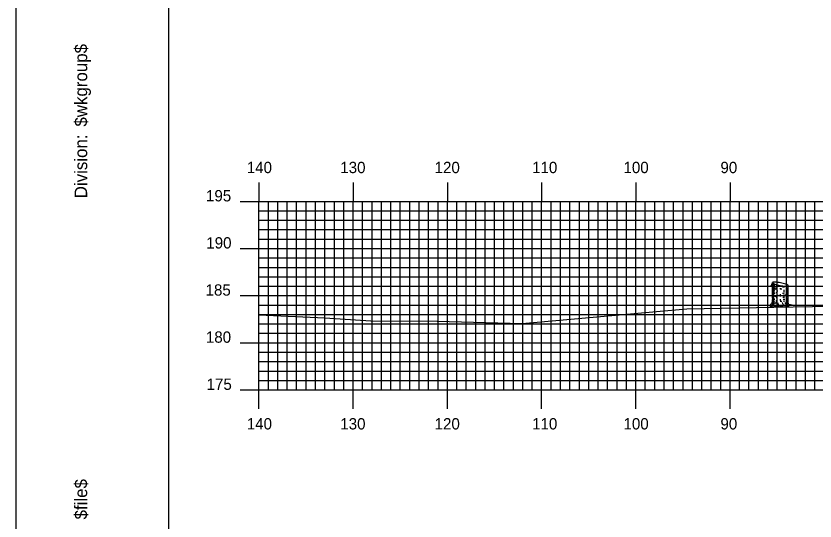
# Model space of a CAD drawing. Extents: x 1825540 to 1825883, y 442591 to 442811.
# Drawn here: x 1825540.1 to 1825624.9, y 442644.7 to 442698.3 of the extents above; entities that cross this region are included whole.
import ezdxf

# ---------------------------------------------------------------- set-up
doc = ezdxf.new("R2010")
doc.units = 0
for name, color, linetype in [('BORDER', 7, 'Continuous'), ('H_V ANNOTATION', 7, 'Continuous'), ('M_Trees_Conifer_Pay', 7, 'Continuous'), ('MAJOR', 7, 'Continuous'), ('MINOR', 7, 'Continuous'), ('PLOT BOUNDARY', 7, 'Continuous'), ('S_Roadway_Centerline', 7, 'Continuous')]:
    doc.layers.add(name, color=color, linetype=linetype)

msp = doc.modelspace()

# ---------------------------------------------------------------- linework, layer by layer
at = {"layer": 'BORDER'}
msp.add_lwpolyline([(1825556.274, 442596.665), (1825876.274, 442596.665), (1825876.274, 442806.665), (1825556.274, 442806.665)], close=True, dxfattribs=at)
at = {"layer": 'M_Trees_Conifer_Pay'}
for p, q in [((1825620.375, 442668.404), (1825620.375, 442670.051)), ((1825620.447, 442669.979), (1825620.447, 442669.816)), ((1825620.564, 442669.918), (1825620.564, 442669.695)), ((1825620.447, 442669.749), (1825620.447, 442669.621)), ((1825620.447, 442669.434), (1825620.447, 442669.098)), ((1825620.447, 442669.061), (1825620.447, 442668.898)), ((1825620.507, 442669.423), (1825620.558, 442669.363)), ((1825620.564, 442669.606), (1825620.564, 442669.559)), ((1825620.564, 442669.224), (1825620.564, 442669.092)), ((1825620.793, 442669.722), (1825620.793, 442669.522)), ((1825620.793, 442669.465), (1825620.793, 442669.376)), ((1825620.793, 442669.028), (1825620.793, 442668.923)), ((1825621.183, 442669.448), (1825621.183, 442669.353)), ((1825621.589, 442669.68), (1825621.589, 442669.512)), ((1825621.589, 442669.275), (1825621.589, 442669.038)), ((1825621.808, 442669.659), (1825621.808, 442669.427)), ((1825621.808, 442669.386), (1825621.808, 442669.312)), ((1825621.934, 442669.667), (1825621.934, 442669.57)), ((1825621.934, 442669.495), (1825621.934, 442669.291)), ((1825621.934, 442669.234), (1825621.934, 442669.034)), ((1825621.992, 442669.678), (1825621.992, 442669.207)), ((1825621.992, 442669.143), (1825621.992, 442668.835)), ((1825622.039, 442667.994), (1825622.039, 442669.716)), ((1825620.447, 442668.851), (1825620.447, 442668.634)), ((1825620.447, 442668.604), (1825620.447, 442668.53)), ((1825620.447, 442668.489), (1825620.447, 442668.316)), ((1825620.564, 442668.981), (1825620.564, 442668.871)), ((1825620.564, 442668.736), (1825620.564, 442668.594)), ((1825620.564, 442668.367), (1825620.564, 442668.194)), ((1825620.793, 442668.556), (1825620.793, 442668.41)), ((1825620.793, 442668.178), (1825620.793, 442668.089)), ((1825621.183, 442668.835), (1825621.183, 442668.76)), ((1825621.183, 442668.736), (1825621.183, 442668.587)), ((1825621.183, 442668.295), (1825621.183, 442668.142)), ((1825621.589, 442668.793), (1825621.589, 442668.641)), ((1825621.589, 442668.598), (1825621.589, 442668.425)), ((1825621.589, 442668.147), (1825621.589, 442667.994)), ((1825621.808, 442668.909), (1825621.808, 442668.77)), ((1825621.808, 442668.499), (1825621.808, 442668.357)), ((1825621.934, 442668.987), (1825621.934, 442668.651)), ((1825621.934, 442668.598), (1825621.934, 442668.462)), ((1825621.934, 442668.363), (1825621.934, 442667.984)), ((1825621.992, 442668.787), (1825621.992, 442668.295)), ((1825621.992, 442668.241), (1825621.992, 442667.994)), ((1825621.371, 442667.537), (1825621.497, 442667.601)), ((1825621.808, 442667.601), (1825621.646, 442667.665)), ((1825621.808, 442668.095), (1825621.808, 442668.001))]:
    msp.add_line(p, q, dxfattribs=at)
for points in [[(1825620.558, 442669.549), (1825620.522, 442669.475), (1825620.474, 442669.532), (1825620.417, 442669.6), (1825620.324, 442669.794), (1825620.26, 442669.841), (1825620.229, 442669.848)], [(1825620.329, 442669.782), (1825620.254, 442669.79), (1825620.182, 442669.691)], [(1825620.544, 442669.296), (1825620.507, 442669.423), (1825620.444, 442669.539), (1825620.413, 442669.606), (1825620.344, 442669.753)], [(1825620.592, 442669.512), (1825620.623, 442669.427), (1825620.627, 442669.36), (1825620.596, 442669.296)], [(1825621.86, 442669.022), (1825621.866, 442669.117), (1825621.823, 442669.094), (1825621.823, 442668.999)], [(1825620.375, 442668.404), (1825620.324, 442668.142), (1825620.308, 442667.869), (1825620.25, 442667.743), (1825620.114, 442667.713), (1825620.344, 442667.675), (1825620.344, 442667.675), (1825620.339, 442667.628), (1825620.091, 442667.533), (1825620.365, 442667.55), (1825620.721, 442667.57), (1825621.043, 442667.56), (1825621.036, 442667.642), (1825621.184, 442667.56), (1825621.371, 442667.537), (1825621.347, 442667.469), (1825621.615, 442667.512), (1825621.835, 442667.486), (1825622.128, 442667.503), (1825621.839, 442667.56), (1825621.808, 442667.601), (1825621.971, 442667.659), (1825622.208, 442667.669), (1825622.449, 442667.669), (1825622.107, 442667.727), (1825622.066, 442667.807), (1825622.039, 442667.994)], [(1825620.449, 442668.262), (1825620.444, 442668.116), (1825620.396, 442668.048), (1825620.386, 442667.848)], [(1825620.721, 442668.623), (1825620.709, 442668.546), (1825620.661, 442668.556), (1825620.674, 442668.723)], [(1825620.549, 442668.116), (1825620.474, 442668.011), (1825620.47, 442667.838), (1825620.344, 442667.675)], [(1825620.507, 442667.622), (1825620.522, 442667.76), (1825620.596, 442667.889)], [(1825620.785, 442668.011), (1825620.775, 442667.885), (1825620.701, 442667.842)], [(1825621.036, 442667.642), (1825620.962, 442667.784), (1825620.952, 442667.885)], [(1825621.524, 442667.713), (1825621.457, 442667.807), (1825621.43, 442667.947)], [(1825621.751, 442667.953), (1825621.751, 442667.821), (1825621.839, 442667.722)], [(1825621.913, 442667.926), (1825621.907, 442667.811), (1825621.961, 442667.722), (1825621.971, 442667.659)], [(1825621.991, 442667.947), (1825622.012, 442667.869), (1825622.033, 442667.774)]]:
    msp.add_lwpolyline(points, dxfattribs=at)
for centre, radius, start, end in [((1825620.398, 442670.051), 0.0226, 168.2806, 179.96855), ((1825620.402, 442670.051), 0.0264, 179.96855, 190.7806), ((1825620.408, 442669.925), 0.0334, 185.78494, 196.05154), ((1825620.398, 442670.051), 0.0226, 156.59265, 168.2806), ((1825620.407, 442670.052), 0.0314, 190.7806, 203.48418), ((1825620.419, 442669.928), 0.0441, 196.05154, 210), ((1825620.401, 442670.05), 0.0264, 145.7806, 156.59265), ((1825620.426, 442670.061), 0.0527, 203.48418, 213.2806), ((1825620.405, 442670.047), 0.0314, 133.07702, 145.7806), ((1825620.435, 442669.937), 0.0624, 210, 228.74941), ((1825620.45, 442670.077), 0.0817, 213.2806, 227.61132), ((1825620.42, 442670.031), 0.0527, 123.2806, 133.07702), ((1825620.436, 442670.007), 0.0817, 108.94987, 123.2806), ((1825620.507, 442670.02), 0.172, 228.74941, 240), ((1825620.564, 442670.201), 0.251, 227.61132, 235.7806), ((1825620.491, 442669.848), 0.251, 100.7806, 108.94987), ((1825620.874, 442670.657), 0.802, 235.7806, 251.94061), ((1825620.594, 442669.306), 0.802, 84.62059, 100.7806), ((1825622.231, 442674.819), 5.179, 251.94061, 258.2806), ((1825620.183, 442664.948), 5.179, 78.2806, 84.62059), ((1825620.183, 442664.948), 5.179, 71.94061, 78.2806), ((1825621.54, 442669.11), 0.802, 55.7806, 71.94061), ((1825620.408, 442669.77), 0.0334, 185.78494, 196.05154), ((1825620.409, 442669.327), 0.0334, 185.78494, 196.05154), ((1825620.419, 442669.773), 0.0441, 196.05154, 210), ((1825620.41, 442669.091), 0.0334, 185.78494, 196.05154), ((1825620.42, 442669.094), 0.0441, 196.05154, 210), ((1825620.435, 442669.783), 0.0624, 210, 228.74941), ((1825620.436, 442669.103), 0.0624, 210, 228.74941), ((1825620.507, 442669.865), 0.172, 228.74941, 240), ((1825620.508, 442669.186), 0.172, 228.74941, 240), ((1825620.706, 442670.21), 0.571, 240, 242.9763), ((1825620.708, 442669.531), 0.571, 240, 242.81041), ((1825620.706, 442669.766), 0.571, 242.95715, 255.55072), ((1825620.706, 442670.365), 0.571, 247.58675, 255.56834), ((1825620.706, 442670.21), 0.571, 255.63335, 261.8968), ((1825621.207, 442673.728), 4.124, 261.8968, 263.76196), ((1825621.209, 442673.495), 4.124, 262.94416, 264.21507), ((1825621.207, 442673.284), 4.124, 264.04957, 266.29476), ((1825622.231, 442674.819), 5.179, 258.2806, 264.62059), ((1825621.209, 442673.495), 4.124, 269.64186, 270), ((1825621.209, 442673.495), 4.124, 270, 271.92488), ((1825621.207, 442673.728), 4.124, 273.26691, 275.3045), ((1825621.821, 442670.461), 0.802, 264.62059, 280.7806), ((1825621.709, 442669.977), 0.571, 282.01543, 293.14027), ((1825621.708, 442669.766), 0.571, 292.94134, 300), ((1825621.924, 442669.919), 0.251, 280.7806, 288.94988), ((1825621.85, 442669.566), 0.251, 47.61132, 55.7806), ((1825621.709, 442669.977), 0.571, 299.66328, 300), ((1825621.709, 442669.531), 0.571, 299.66328, 300), ((1825621.909, 442669.632), 0.172, 300, 311.25059), ((1825621.909, 442669.186), 0.172, 300, 311.25059), ((1825621.979, 442669.76), 0.0817, 288.94988, 303.2806), ((1825621.964, 442669.69), 0.0817, 33.2806, 47.61132), ((1825621.981, 442669.55), 0.0624, 311.25059, 330), ((1825621.981, 442669.103), 0.0624, 311.25059, 330), ((1825621.994, 442669.735), 0.0527, 303.2806, 313.07702), ((1825622.009, 442669.72), 0.0314, 313.07702, 325.7806), ((1825621.988, 442669.706), 0.0527, 23.48418, 33.2806), ((1825622.013, 442669.717), 0.0264, 325.7806, 336.59265), ((1825621.997, 442669.541), 0.0441, 330, 343.94846), ((1825621.997, 442669.094), 0.0441, 330, 343.94846), ((1825622.008, 442669.715), 0.0314, 10.7806, 23.48418), ((1825622.017, 442669.716), 0.0226, 336.59265, 348.2806), ((1825622.013, 442669.716), 0.0264, 359.96855, 10.7806), ((1825622.017, 442669.716), 0.0226, 348.2806, 359.96855), ((1825622.007, 442669.538), 0.0334, 0, 16.05154), ((1825622.007, 442669.538), 0.0334, 343.94846, 360), ((1825622.007, 442669.091), 0.0334, 0, 16.05154), ((1825622.007, 442669.091), 0.0334, 343.94846, 360), ((1825620.41, 442668.881), 0.0334, 185.78494, 196.05154), ((1825620.41, 442668.446), 0.0334, 185.78494, 196.05154), ((1825620.42, 442668.884), 0.0441, 196.05154, 210), ((1825620.42, 442668.449), 0.0441, 196.05154, 210), ((1825620.436, 442668.893), 0.0624, 210, 228.74941), ((1825620.436, 442668.458), 0.0624, 210, 228.74941), ((1825620.508, 442668.975), 0.172, 228.74941, 240), ((1825620.508, 442668.541), 0.172, 228.74941, 240), ((1825620.708, 442669.321), 0.571, 240, 242.81041), ((1825620.708, 442668.886), 0.571, 240, 250.70928), ((1825620.708, 442668.691), 0.571, 242.72792, 251.49327), ((1825620.708, 442669.084), 0.571, 242.81041, 254.60173), ((1825620.708, 442669.531), 0.571, 253.07038, 261.8968), ((1825621.209, 442673.048), 4.124, 261.8968, 262.38753), ((1825621.209, 442672.838), 4.124, 264.54309, 266.85066), ((1825621.209, 442672.838), 4.124, 269.64186, 270), ((1825621.209, 442673.048), 4.124, 273.33241, 275.91902), ((1825621.209, 442672.601), 4.124, 273.68066, 275.28397), ((1825621.209, 442672.404), 4.124, 274.16025, 276.50094), ((1825621.209, 442672.838), 4.124, 276.85262, 278.1032), ((1825621.709, 442669.321), 0.571, 278.1032, 280.72928), ((1825621.709, 442669.321), 0.571, 293.14027, 300), ((1825621.709, 442669.084), 0.571, 293.14027, 300), ((1825621.72, 442668.892), 0.571, 291.97323, 298.76314), ((1825621.709, 442668.691), 0.571, 293.14027, 300), ((1825621.909, 442668.975), 0.172, 300, 311.25059), ((1825621.909, 442668.739), 0.172, 300, 311.25059), ((1825621.909, 442668.345), 0.172, 300, 311.25059), ((1825621.981, 442668.893), 0.0624, 311.25059, 330), ((1825621.981, 442668.656), 0.0624, 311.25059, 330), ((1825621.981, 442668.263), 0.0624, 311.25059, 330), ((1825621.997, 442668.884), 0.0441, 330, 343.94846), ((1825621.997, 442668.647), 0.0441, 330, 343.94846), ((1825621.997, 442668.254), 0.0441, 330, 343.94846), ((1825622.007, 442668.881), 0.0334, 0, 16.05154), ((1825622.007, 442668.881), 0.0334, 343.94846, 360), ((1825622.007, 442668.644), 0.0334, 0, 16.05154), ((1825622.007, 442668.644), 0.0334, 343.94846, 360), ((1825622.007, 442668.446), 0.0334, 0, 16.05154), ((1825622.007, 442668.251), 0.0334, 0, 16.05154), ((1825622.007, 442668.251), 0.0334, 343.94846, 360), ((1825620.41, 442668.03), 0.0334, 185.78494, 196.05154), ((1825620.42, 442668.033), 0.0441, 196.05154, 210), ((1825620.436, 442668.043), 0.0624, 210, 228.74941), ((1825620.508, 442668.125), 0.172, 228.74941, 240), ((1825620.708, 442668.47), 0.571, 258.36297, 261.8968), ((1825621.209, 442671.988), 4.124, 261.8968, 262.63158), ((1825621.209, 442672.208), 4.124, 263.21039, 264.21507), ((1825621.209, 442672.208), 4.124, 269.86721, 270), ((1825621.209, 442672.208), 4.124, 270, 272.18834), ((1825621.209, 442671.988), 4.124, 276.48798, 277.55621), ((1825621.709, 442668.47), 0.571, 295.46862, 300), ((1825621.909, 442668.125), 0.172, 300, 311.25059), ((1825621.981, 442668.043), 0.0624, 311.25059, 330), ((1825621.997, 442668.033), 0.0441, 330, 343.94846), ((1825622.007, 442668.03), 0.0334, 0, 16.05154), ((1825622.007, 442668.03), 0.0334, 343.94846, 360)]:
    msp.add_arc(centre, radius, start, end, dxfattribs=at)
at = {"layer": 'MAJOR'}
for p, q in [((1825565.874, 442680.669), (1825565.874, 442678.665)), ((1825575.874, 442680.669), (1825575.874, 442678.665)), ((1825585.874, 442680.669), (1825585.874, 442678.665)), ((1825595.874, 442680.669), (1825595.874, 442678.665)), ((1825605.874, 442680.669), (1825605.874, 442678.665)), ((1825615.874, 442680.669), (1825615.874, 442678.665)), ((1825563.87, 442678.665), (1825565.874, 442678.665)), ((1825565.874, 442678.665), (1825845.874, 442678.665)), ((1825565.874, 442658.665), (1825565.874, 442678.665)), ((1825565.874, 442658.665), (1825565.874, 442678.665)), ((1825565.874, 442678.665), (1825845.874, 442678.665)), ((1825575.874, 442658.665), (1825575.874, 442678.665)), ((1825585.874, 442658.665), (1825585.874, 442678.665)), ((1825595.874, 442658.665), (1825595.874, 442678.665)), ((1825605.874, 442658.665), (1825605.874, 442678.665)), ((1825615.874, 442658.665), (1825615.874, 442678.665)), ((1825563.87, 442673.665), (1825565.874, 442673.665)), ((1825565.874, 442673.665), (1825845.874, 442673.665)), ((1825563.87, 442668.665), (1825565.874, 442668.665)), ((1825565.874, 442668.665), (1825845.874, 442668.665)), ((1825563.87, 442663.665), (1825565.874, 442663.665)), ((1825565.874, 442663.665), (1825845.874, 442663.665)), ((1825563.87, 442658.665), (1825565.874, 442658.665)), ((1825565.874, 442658.665), (1825845.874, 442658.665)), ((1825565.874, 442658.665), (1825845.874, 442658.665)), ((1825565.874, 442656.661), (1825565.874, 442658.665)), ((1825575.874, 442656.661), (1825575.874, 442658.665)), ((1825585.874, 442656.661), (1825585.874, 442658.665)), ((1825595.874, 442656.661), (1825595.874, 442658.665)), ((1825605.874, 442656.661), (1825605.874, 442658.665)), ((1825615.874, 442656.661), (1825615.874, 442658.665))]:
    msp.add_line(p, q, dxfattribs=at)
at = {"layer": 'MINOR'}
for p, q in [((1825566.874, 442658.665), (1825566.874, 442678.665)), ((1825567.874, 442658.665), (1825567.874, 442678.665)), ((1825568.874, 442658.665), (1825568.874, 442678.665)), ((1825569.874, 442658.665), (1825569.874, 442678.665)), ((1825570.874, 442658.665), (1825570.874, 442678.665)), ((1825571.874, 442658.665), (1825571.874, 442678.665)), ((1825572.874, 442658.665), (1825572.874, 442678.665)), ((1825573.874, 442658.665), (1825573.874, 442678.665)), ((1825574.874, 442658.665), (1825574.874, 442678.665)), ((1825576.874, 442658.665), (1825576.874, 442678.665)), ((1825577.874, 442658.665), (1825577.874, 442678.665)), ((1825578.874, 442658.665), (1825578.874, 442678.665)), ((1825579.874, 442658.665), (1825579.874, 442678.665)), ((1825580.874, 442658.665), (1825580.874, 442678.665)), ((1825581.874, 442658.665), (1825581.874, 442678.665)), ((1825582.874, 442658.665), (1825582.874, 442678.665)), ((1825583.874, 442658.665), (1825583.874, 442678.665)), ((1825584.874, 442658.665), (1825584.874, 442678.665)), ((1825586.874, 442658.665), (1825586.874, 442678.665)), ((1825587.874, 442658.665), (1825587.874, 442678.665)), ((1825588.874, 442658.665), (1825588.874, 442678.665)), ((1825589.874, 442658.665), (1825589.874, 442678.665)), ((1825590.874, 442658.665), (1825590.874, 442678.665)), ((1825591.874, 442658.665), (1825591.874, 442678.665)), ((1825592.874, 442658.665), (1825592.874, 442678.665)), ((1825593.874, 442658.665), (1825593.874, 442678.665)), ((1825594.874, 442658.665), (1825594.874, 442678.665)), ((1825596.874, 442658.665), (1825596.874, 442678.665)), ((1825597.874, 442658.665), (1825597.874, 442678.665)), ((1825598.874, 442658.665), (1825598.874, 442678.665)), ((1825599.874, 442658.665), (1825599.874, 442678.665)), ((1825600.874, 442658.665), (1825600.874, 442678.665)), ((1825601.874, 442658.665), (1825601.874, 442678.665)), ((1825602.874, 442658.665), (1825602.874, 442678.665)), ((1825603.874, 442658.665), (1825603.874, 442678.665)), ((1825604.874, 442658.665), (1825604.874, 442678.665)), ((1825606.874, 442658.665), (1825606.874, 442678.665)), ((1825607.874, 442658.665), (1825607.874, 442678.665)), ((1825608.874, 442658.665), (1825608.874, 442678.665)), ((1825609.874, 442658.665), (1825609.874, 442678.665)), ((1825610.874, 442658.665), (1825610.874, 442678.665)), ((1825611.874, 442658.665), (1825611.874, 442678.665)), ((1825612.874, 442658.665), (1825612.874, 442678.665)), ((1825613.874, 442658.665), (1825613.874, 442678.665)), ((1825614.874, 442658.665), (1825614.874, 442678.665)), ((1825616.874, 442658.665), (1825616.874, 442678.665)), ((1825617.874, 442658.665), (1825617.874, 442678.665)), ((1825618.874, 442658.665), (1825618.874, 442678.665)), ((1825619.874, 442658.665), (1825619.874, 442678.665)), ((1825620.874, 442658.665), (1825620.874, 442678.665)), ((1825621.874, 442658.665), (1825621.874, 442678.665)), ((1825622.874, 442658.665), (1825622.874, 442678.665)), ((1825623.874, 442658.665), (1825623.874, 442678.665)), ((1825624.874, 442658.665), (1825624.874, 442678.665)), ((1825565.874, 442677.665), (1825845.874, 442677.665)), ((1825565.874, 442677.665), (1825567.878, 442677.665)), ((1825565.874, 442676.665), (1825845.874, 442676.665)), ((1825565.874, 442676.665), (1825567.878, 442676.665)), ((1825565.874, 442675.665), (1825845.874, 442675.665)), ((1825565.874, 442675.665), (1825567.878, 442675.665)), ((1825565.874, 442674.665), (1825845.874, 442674.665)), ((1825565.874, 442674.665), (1825567.878, 442674.665)), ((1825565.874, 442672.665), (1825845.874, 442672.665)), ((1825565.874, 442672.665), (1825567.878, 442672.665)), ((1825565.874, 442671.665), (1825845.874, 442671.665)), ((1825565.874, 442671.665), (1825567.878, 442671.665)), ((1825565.874, 442670.665), (1825845.874, 442670.665)), ((1825565.874, 442670.665), (1825567.878, 442670.665)), ((1825565.874, 442669.665), (1825845.874, 442669.665)), ((1825565.874, 442669.665), (1825567.878, 442669.665)), ((1825565.874, 442667.665), (1825845.874, 442667.665)), ((1825565.874, 442667.665), (1825567.878, 442667.665)), ((1825565.874, 442666.665), (1825845.874, 442666.665)), ((1825565.874, 442666.665), (1825567.878, 442666.665)), ((1825565.874, 442665.665), (1825845.874, 442665.665)), ((1825565.874, 442665.665), (1825567.878, 442665.665)), ((1825565.874, 442664.665), (1825845.874, 442664.665)), ((1825565.874, 442664.665), (1825567.878, 442664.665)), ((1825565.874, 442662.665), (1825845.874, 442662.665)), ((1825565.874, 442662.665), (1825567.878, 442662.665)), ((1825565.874, 442661.665), (1825845.874, 442661.665)), ((1825565.874, 442661.665), (1825567.878, 442661.665)), ((1825565.874, 442660.665), (1825845.874, 442660.665)), ((1825565.874, 442660.665), (1825567.878, 442660.665)), ((1825565.874, 442659.665), (1825845.874, 442659.665)), ((1825565.874, 442659.665), (1825567.878, 442659.665))]:
    msp.add_line(p, q, dxfattribs=at)
at = {"layer": 'PLOT BOUNDARY'}
msp.add_lwpolyline([(1825540.087, 442590.547), (1825880.087, 442590.547), (1825880.087, 442810.547), (1825540.087, 442810.547)], close=True, dxfattribs=at)
msp.add_lwpolyline([(1825540.087, 442590.547), (1825880.087, 442590.547), (1825880.087, 442810.547), (1825540.087, 442810.547)], close=True, dxfattribs=at)
at = {"layer": 'S_Roadway_Centerline'}
msp.add_lwpolyline([(1825565.874, 442666.629), (1825572.871, 442666.308), (1825577.737, 442665.976), (1825584.774, 442665.954), (1825593.812, 442665.7), (1825608.063, 442666.971), (1825611.284, 442667.268), (1825620.521, 442667.443), (1825626.675, 442667.534)], dxfattribs=at)

# ---------------------------------------------------------------- texts
at = {"layer": 'BORDER'}
for s, p in [('$wkgroup$', (1825547.644, 442686.604)), ('Division:', (1825547.644, 442678.997)), ('$file$', (1825547.644, 442644.916))]:
    msp.add_text(s, height=1.3392, rotation=90, dxfattribs=at).set_placement(p)
at = {"layer": 'H_V ANNOTATION'}
for s, p in [('140', (1825564.579, 442681.665)), ('130', (1825574.504, 442681.665)), ('120', (1825584.515, 442681.665)), ('110', (1825594.857, 442681.665)), ('100', (1825604.557, 442681.665)), ('90', (1825614.846, 442681.665)), ('195', (1825560.252, 442678.665)), ('190', (1825560.284, 442673.665)), ('185', (1825560.209, 442668.665)), ('180', (1825560.241, 442663.665)), ('175', (1825560.316, 442658.665)), ('140', (1825564.579, 442654.465)), ('130', (1825574.504, 442654.465)), ('120', (1825584.515, 442654.465)), ('110', (1825594.857, 442654.465)), ('100', (1825604.557, 442654.465)), ('90', (1825614.846, 442654.465))]:
    msp.add_text(s, height=1.2, dxfattribs=at).set_placement(p)
at = {"layer": 'MAJOR'}
msp.add_text('-', height=0.012, dxfattribs=at).set_placement((1825565.865, 442658.665))

doc.saveas('drawing.dxf')
